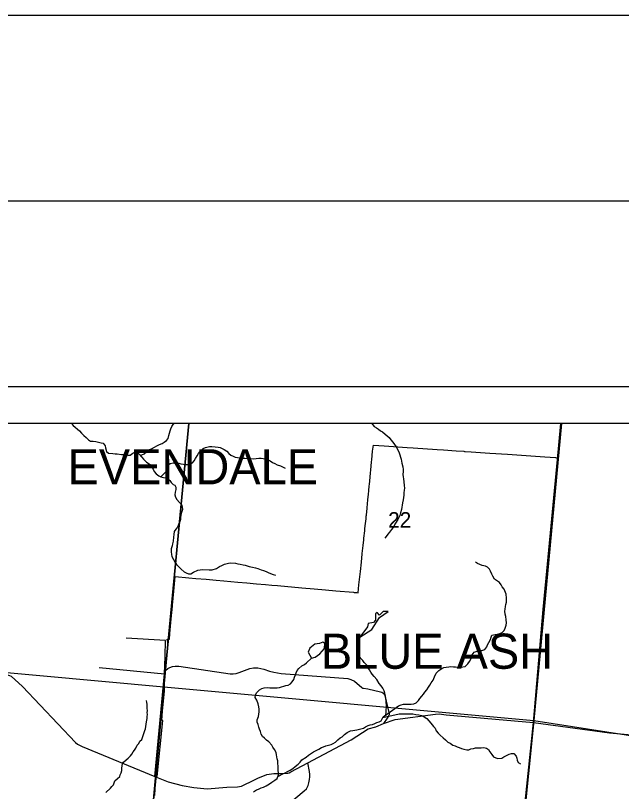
# Model space of a CAD drawing. Extents: x 0 to 34, y -3.9 to 26.2.
# Drawn here: x 4.778 to 6.412, y 19.908 to 22 of the extents above; entities that cross this region are included whole.
import ezdxf

# ---------------------------------------------------------------- set-up
doc = ezdxf.new("R2010")
doc.units = 0
for name, color, linetype in [('GM_X_City_Street', 7, 'Continuous'), ('GM_X_Corporation_Text', 7, 'Continuous'), ('GM_X_County_Road', 7, 'Continuous'), ('GM_X_Interchange_Ramps', 7, 'Continuous'), ('GM_X_Interstate_Route', 7, 'Continuous'), ('GM_X_Minor_Lake', 7, 'Continuous'), ('GM_X_Minor_River', 7, 'Continuous'), ('GM_X_Section', 7, 'Continuous'), ('GM_X_Section_Text', 7, 'Continuous'), ('GM_X_State_Shield', 7, 'Continuous'), ('SH_Border', 7, 'Continuous'), ('SH_Cut_Line', 7, 'Continuous'), ('SH_Data', 7, 'Continuous')]:
    doc.layers.add(name, color=color, linetype=linetype)

msp = doc.modelspace()

# ---------------------------------------------------------------- linework, layer by layer
at = {"layer": 'GM_X_City_Street'}
for p, q in [((6.2393, 20.8032), (6.2483, 20.9)), ((5.0032, 20.2422), (5.1797, 20.2252))]:
    msp.add_line(p, q, dxfattribs=at)
for points in [[(6.2305, 19.6109), (6.2157, 19.6127), (6.1964, 19.617), (6.1806, 19.6226), (6.1712, 19.6285), (6.163, 19.6348), (6.1565, 19.6421), (6.1533, 19.6464), (6.1505, 19.6517), (6.1459, 19.665), (6.1443, 19.6717), (6.1419, 19.6812), (6.1399, 19.6998), (6.1394, 19.7226), (6.1444, 19.8016), (6.1745, 20.0934), (6.2008, 20.3987), (6.2393, 20.8032)], [(5.1797, 20.2252), (5.1811, 20.2714), (5.1826, 20.3148), (5.076, 20.321)], [(5.1535, 19.9477), (5.1797, 20.2252), (5.1828, 20.2339), (5.1882, 20.2391), (5.1936, 20.2424), (5.2016, 20.2449), (5.2088, 20.2455), (5.2183, 20.2453), (5.3565, 20.2252), (5.3652, 20.2247), (5.3728, 20.2256), (5.3808, 20.2289), (5.4099, 20.2393), (5.4194, 20.2414), (5.4316, 20.2415), (5.4478, 20.2373), (5.4629, 20.2321), (5.4746, 20.2292), (5.4939, 20.2257), (5.6739, 20.212), (5.6819, 20.2099), (5.6924, 20.2051), (5.7114, 20.188), (5.7142, 20.1864), (5.7163, 20.186), (5.728, 20.1846), (5.762, 20.1767), (5.7654, 20.1754), (5.7681, 20.1739), (5.7715, 20.1706), (5.7733, 20.1681), (5.774, 20.1668), (5.7859, 20.1173), (5.7859, 20.1166), (5.7854, 20.1147), (5.7847, 20.1128), (5.7804, 20.1056), (5.7702, 20.091)], [(5.4375, 19.7631), (5.442, 19.7697), (5.468, 19.808), (5.4947, 19.853), (5.5041, 19.865), (5.5168, 19.8761), (5.5562, 19.9095), (5.5623, 19.9152), (5.5647, 19.9188), (5.5668, 19.9243), (5.5688, 19.9312), (5.5706, 19.9398), (5.5714, 19.9471), (5.5714, 19.9539), (5.5706, 19.9616), (5.5666, 19.9852)]]:
    msp.add_lwpolyline(points, dxfattribs=at)
at = {"layer": 'GM_X_County_Road'}
msp.add_line((6.1745, 20.0934), (6.3797, 20.0659), dxfattribs=at)
for points in [[(4.3628, 20.2608), (4.7594, 20.2214), (4.7613, 20.2207), (4.7666, 20.2189), (4.7965, 20.1906), (4.9395, 20.0396), (4.9451, 20.0349), (4.9572, 20.0286), (5.1535, 19.9477)], [(5.1535, 19.9477), (5.1896, 19.9336), (5.227, 19.9241), (5.2592, 19.9181), (5.2948, 19.9147), (5.3473, 19.9196), (5.3765, 19.9201), (5.3873, 19.9223), (5.3948, 19.9254), (5.4155, 19.9356), (5.4313, 19.9437), (5.4558, 19.9534), (5.4748, 19.956), (5.4983, 19.9563), (5.51, 19.9568), (5.512, 19.9571), (5.5159, 19.9584), (5.5204, 19.9604), (5.5358, 19.9688), (5.5666, 19.9852), (5.6828, 20.0473), (5.7285, 20.0771), (5.7499, 20.082), (5.7702, 20.091), (5.8015, 20.1018), (5.9104, 20.1162), (5.9207, 20.1167), (5.9396, 20.1148), (6.1745, 20.0934)], [(6.3797, 20.0659), (6.4489, 20.0597), (6.5081, 20.0476)]]:
    msp.add_lwpolyline(points, dxfattribs=at)
at = {"layer": 'GM_X_Interchange_Ramps'}
msp.add_lwpolyline([(5.1532, 19.8973), (5.1549, 19.9158), (5.1576, 19.9437), (5.1579, 19.9491), (5.1602, 19.948), (5.1754, 20.0993), (5.1721, 20.0997), (5.1744, 20.1241), (5.1796, 20.1794), (5.1799, 20.1851), (5.18, 20.2008), (5.1804, 20.2075), (5.1842, 20.2474), (5.1897, 20.3059), (5.1865, 20.3188), (5.1927, 20.3183), (5.1941, 20.3337), (5.1959, 20.3535), (5.1968, 20.3632), (5.1977, 20.3723), (5.1994, 20.3911), (5.2, 20.3967), (5.2012, 20.41), (5.2029, 20.4289), (5.2047, 20.4477), (5.2084, 20.4873), (5.2452, 20.484), (5.2641, 20.4824), (5.2924, 20.4799), (5.3186, 20.4776), (5.3394, 20.4758), (5.3584, 20.4741), (5.3773, 20.4724), (5.4021, 20.4702), (5.4274, 20.468), (5.452, 20.4658), (5.4694, 20.4643), (5.4848, 20.463), (5.5504, 20.4572), (5.5833, 20.4543), (5.6135, 20.4516), (5.6418, 20.4491), (5.6894, 20.4449), (5.6908, 20.4447), (5.698, 20.4441), (5.7017, 20.4438), (5.704, 20.4652), (5.7078, 20.5007), (5.7105, 20.5258), (5.7129, 20.5482), (5.713, 20.5491), (5.7153, 20.5709), (5.717, 20.5863), (5.7174, 20.5904), (5.7196, 20.6109), (5.7203, 20.6172), (5.7217, 20.6305), (5.7231, 20.6427), (5.7238, 20.6501), (5.724, 20.6525), (5.725, 20.6624), (5.7259, 20.6711), (5.726, 20.6726), (5.7281, 20.6944), (5.7296, 20.7096), (5.7304, 20.7186), (5.7317, 20.7322), (5.7321, 20.7359), (5.734, 20.7551), (5.7351, 20.7671), (5.7359, 20.7743), (5.7382, 20.7968), (5.7387, 20.802), (5.7409, 20.8252), (5.7429, 20.8417), (5.7717, 20.8397), (5.8342, 20.8354), (5.8499, 20.8344), (5.9151, 20.8299), (5.9321, 20.8287), (5.9661, 20.8264), (5.9865, 20.825), (5.9888, 20.8248), (5.9903, 20.8247), (6.0069, 20.8236), (6.0443, 20.821), (6.0572, 20.8201), (6.105, 20.8169), (6.2053, 20.81), (6.2341, 20.808), (6.2367, 20.8078), (6.2424, 20.8074), (6.2473, 20.8629), (6.2507, 20.9), (3.4963, 20.9)], dxfattribs=at)
at = {"layer": 'GM_X_Interstate_Route'}
msp.add_lwpolyline([(8.9, 20.9), (3.1989, 20.9)], dxfattribs=at)
at = {"layer": 'GM_X_Minor_Lake'}
for p, q in [((5.727, 20.3513), (5.7067, 20.3234)), ((5.5669, 20.2838), (5.576, 20.2668))]:
    msp.add_line(p, q, dxfattribs=at)
for points in [[(5.7067, 20.3234), (5.7391, 20.3446), (5.7591, 20.3768), (5.7826, 20.3931), (5.7693, 20.3926), (5.7592, 20.3829), (5.7529, 20.3899), (5.7483, 20.3869), (5.7483, 20.3698), (5.7429, 20.3631), (5.7291, 20.3611), (5.727, 20.3513)], [(5.576, 20.2668), (5.5856, 20.2701), (5.5983, 20.279), (5.6107, 20.2932), (5.6118, 20.3064), (5.6069, 20.3107), (5.5977, 20.3071), (5.5851, 20.3051), (5.572, 20.2943), (5.5669, 20.2838)]]:
    msp.add_lwpolyline(points, dxfattribs=at)
at = {"layer": 'GM_X_Minor_River'}
for points in [[(4.9291, 20.9), (4.9338, 20.8945), (4.939, 20.8905), (4.9453, 20.8849), (4.9504, 20.8798), (4.9558, 20.8735), (4.962, 20.8675), (4.9687, 20.8623), (4.9745, 20.856), (4.9805, 20.8527), (4.9873, 20.8524), (4.9945, 20.8513), (5.0013, 20.8499), (5.0092, 20.8481), (5.0144, 20.8467), (5.0198, 20.8396), (5.0208, 20.8343), (5.023, 20.8243), (5.0286, 20.8199), (5.0399, 20.819), (5.0464, 20.8184), (5.052, 20.8178), (5.0638, 20.8165), (5.0695, 20.8163), (5.0748, 20.8153), (5.0808, 20.8143), (5.0869, 20.8148), (5.0947, 20.8198), (5.1001, 20.823), (5.1062, 20.8224), (5.1128, 20.8156), (5.1186, 20.8089), (5.1233, 20.8034), (5.1314, 20.7959), (5.141, 20.789), (5.1449, 20.7835), (5.1489, 20.7769), (5.1517, 20.7707), (5.1575, 20.7644), (5.1648, 20.7584), (5.1701, 20.7559), (5.1772, 20.7544), (5.1836, 20.753), (5.1893, 20.7509), (5.1944, 20.7465), (5.1972, 20.7407), (5.2027, 20.7355), (5.2079, 20.7334), (5.2104, 20.7279), (5.2102, 20.7223), (5.2087, 20.7147), (5.2077, 20.7079), (5.209, 20.7014), (5.2125, 20.6952), (5.2198, 20.6865), (5.2253, 20.6813), (5.2269, 20.6756), (5.2278, 20.6683), (5.2243, 20.657), (5.2233, 20.6518), (5.2227, 20.6461), (5.2225, 20.6408), (5.2212, 20.6355), (5.2174, 20.6273), (5.2145, 20.6206), (5.2101, 20.6147), (5.2061, 20.6084), (5.205, 20.6008), (5.2043, 20.5936), (5.2028, 20.5831), (5.2013, 20.5755), (5.2004, 20.5702), (5.1978, 20.5624), (5.1974, 20.5536), (5.1987, 20.5467), (5.1996, 20.5414), (5.2035, 20.5332), (5.2085, 20.5254), (5.2121, 20.5196), (5.2194, 20.5128), (5.2248, 20.5069), (5.2329, 20.4997), (5.2381, 20.4972), (5.2441, 20.495), (5.2506, 20.4948), (5.258, 20.4994), (5.2692, 20.5043), (5.2761, 20.5055), (5.2822, 20.506), (5.3004, 20.5052), (5.3084, 20.5057), (5.3196, 20.5094), (5.3281, 20.514), (5.3339, 20.5168)], [(5.1141, 20.8141), (5.1246, 20.8182), (5.1309, 20.8232), (5.1391, 20.8294), (5.1446, 20.8318), (5.1523, 20.836), (5.1589, 20.8396), (5.1663, 20.8431), (5.1733, 20.8462), (5.1791, 20.8498), (5.1846, 20.8537), (5.1894, 20.8596), (5.1916, 20.8675), (5.1933, 20.8739), (5.1947, 20.8799), (5.1969, 20.8859), (5.1997, 20.8915), (5.2034, 20.897), (5.2055, 20.9)], [(5.7382, 20.9), (5.7385, 20.8995), (5.7451, 20.892), (5.7514, 20.8883), (5.757, 20.885), (5.7625, 20.8806), (5.7677, 20.8774), (5.7747, 20.8714), (5.7802, 20.8666), (5.7853, 20.8618), (5.7904, 20.8559), (5.7951, 20.85), (5.8002, 20.8429), (5.8048, 20.8367), (5.8087, 20.8285), (5.8126, 20.8211), (5.8147, 20.8157), (5.8159, 20.8096), (5.8176, 20.8042), (5.8186, 20.7988), (5.8198, 20.7931), (5.8221, 20.7835), (5.8234, 20.7762), (5.8235, 20.7709), (5.8228, 20.7622), (5.8229, 20.7561), (5.8239, 20.7503), (5.8247, 20.7431), (5.8262, 20.7331), (5.8267, 20.7259), (5.8261, 20.7198), (5.8254, 20.713), (5.8248, 20.707), (5.8242, 20.7001), (5.8232, 20.6941), (5.8213, 20.6858), (5.8207, 20.6798), (5.8197, 20.6745), (5.8187, 20.6677), (5.8164, 20.6587), (5.8147, 20.6523), (5.8114, 20.6463), (5.8089, 20.6411), (5.8041, 20.6337), (5.8008, 20.6281), (5.7983, 20.6225), (5.7915, 20.6137), (5.7863, 20.6071), (5.7819, 20.6019), (5.7775, 20.5957), (5.7742, 20.5905)], [(5.1701, 20.7559), (5.184, 20.7709), (5.1862, 20.7803), (5.188, 20.7863), (5.1947, 20.7917), (5.2031, 20.794), (5.2126, 20.7932), (5.2179, 20.7926), (5.2235, 20.7913), (5.2307, 20.7906), (5.2375, 20.7895), (5.244, 20.7897), (5.2494, 20.7909), (5.2552, 20.7937), (5.2596, 20.7989), (5.2636, 20.8056), (5.2673, 20.813), (5.271, 20.8193), (5.277, 20.8263), (5.284, 20.8321), (5.2899, 20.8353), (5.3006, 20.8382), (5.3071, 20.8383), (5.3162, 20.8372), (5.3241, 20.8365), (5.3298, 20.8351), (5.3354, 20.8326), (5.3406, 20.8297), (5.3476, 20.8256), (5.3531, 20.8193), (5.3582, 20.8146), (5.3646, 20.812), (5.3706, 20.8095), (5.3762, 20.8081), (5.3826, 20.8075), (5.3894, 20.8068), (5.3959, 20.8061), (5.4027, 20.8059), (5.4099, 20.8052), (5.4194, 20.8048), (5.4266, 20.8052), (5.4339, 20.8065), (5.4403, 20.8062), (5.4456, 20.8056), (5.4513, 20.805), (5.4573, 20.8028), (5.4644, 20.7991), (5.4711, 20.795), (5.4774, 20.7921), (5.4837, 20.7888), (5.4927, 20.7854), (5.4994, 20.7821), (5.5054, 20.7795)], [(5.7719, 20.1111), (5.8107, 20.1385), (5.8181, 20.1416), (5.8246, 20.1432), (5.8326, 20.1429), (5.8447, 20.1428), (5.8516, 20.144), (5.8586, 20.1468), (5.8649, 20.153), (5.8685, 20.1585), (5.8737, 20.1644), (5.8785, 20.1699), (5.8821, 20.1758), (5.8873, 20.1821), (5.8918, 20.1891), (5.8954, 20.1946), (5.8991, 20.2006), (5.9043, 20.208), (5.9077, 20.2169), (5.9123, 20.2266), (5.9198, 20.2339), (5.9276, 20.2389), (5.933, 20.2417), (5.9395, 20.243), (5.946, 20.2439), (5.9521, 20.2447), (5.9586, 20.2441), (5.9646, 20.2438), (5.9714, 20.2432), (5.9787, 20.2429), (5.9844, 20.2434), (5.9901, 20.2443), (5.9976, 20.2516), (6.0024, 20.2579), (6.0057, 20.2646), (6.0071, 20.2698), (6.0089, 20.2766), (6.0144, 20.2832), (6.0229, 20.2863), (6.0298, 20.2879), (6.0351, 20.2877), (6.0432, 20.2904), (6.0488, 20.2974), (6.0506, 20.3034), (6.0542, 20.3093), (6.0587, 20.3175), (6.0605, 20.3239), (6.0622, 20.3291), (6.0718, 20.331), (6.0775, 20.3319), (6.0837, 20.3339), (6.0899, 20.3367), (6.0958, 20.3418), (6.0987, 20.3481), (6.1006, 20.3564), (6.1015, 20.3621), (6.1007, 20.3709), (6.0999, 20.3793), (6.0983, 20.3862), (6.0978, 20.3938), (6.0984, 20.3991), (6.0995, 20.4066), (6.1005, 20.4123), (6.1015, 20.4183), (6.1015, 20.4294), (6.1008, 20.4397), (6.096, 20.4535), (6.0902, 20.4595), (6.0874, 20.4653), (6.0834, 20.4708), (6.0778, 20.4744), (6.0697, 20.4805), (6.0647, 20.4887), (6.0627, 20.4941), (6.0592, 20.5018), (6.056, 20.5073), (6.0508, 20.5124), (6.0449, 20.5153), (6.0362, 20.5168), (6.0298, 20.5194), (6.0235, 20.5227), (6.0183, 20.5263)], [(5.3339, 20.5168), (5.3413, 20.521), (5.3524, 20.5232), (5.3586, 20.5245), (5.3714, 20.5232), (5.3778, 20.5218), (5.3839, 20.5208), (5.3918, 20.5189), (5.3974, 20.5176), (5.4027, 20.5158), (5.4083, 20.5148), (5.4174, 20.5129), (5.4249, 20.5111), (5.4317, 20.5093), (5.4406, 20.5055), (5.4467, 20.5037), (5.4534, 20.5012), (5.4608, 20.4974), (5.4728, 20.4931), (5.4792, 20.491)], [(5.4848, 19.9468), (5.4968, 19.9546), (5.5053, 19.9581), (5.5115, 19.9616), (5.5185, 19.9651), (5.5259, 19.9694), (5.5318, 19.9748), (5.5397, 19.9817), (5.5452, 19.9872), (5.5504, 19.9931), (5.5613, 20.0002), (5.5676, 20.0053), (5.5738, 20.0092), (5.5816, 20.0142), (5.589, 20.0185), (5.596, 20.022), (5.6026, 20.0259), (5.608, 20.0279), (5.615, 20.0307), (5.6223, 20.0327), (5.6288, 20.0347), (5.6342, 20.0367), (5.6404, 20.0406), (5.6475, 20.0468), (5.6531, 20.0523), (5.6585, 20.0555), (5.6648, 20.0617), (5.6726, 20.0667), (5.6815, 20.0713), (5.6873, 20.0722), (5.6927, 20.0735), (5.698, 20.074), (5.7091, 20.0766), (5.7164, 20.0782), (5.7219, 20.0821), (5.7285, 20.0853), (5.7342, 20.0873), (5.7404, 20.0882), (5.7469, 20.0906), (5.7523, 20.0934), (5.7589, 20.0958), (5.7643, 20.0986), (5.7668, 20.1038), (5.7697, 20.1094), (5.7767, 20.1148), (5.7774, 20.122), (5.7782, 20.141), (5.7776, 20.1467), (5.7775, 20.152), (5.7769, 20.1581), (5.7753, 20.1654), (5.7737, 20.1731), (5.7717, 20.1793), (5.7682, 20.1863), (5.7635, 20.1922), (5.7588, 20.1992), (5.7524, 20.2097), (5.7447, 20.218), (5.7393, 20.2243), (5.7361, 20.2298), (5.7325, 20.2356), (5.7282, 20.2423), (5.725, 20.2485), (5.7184, 20.2552), (5.7145, 20.2607), (5.7094, 20.2659), (5.7036, 20.2741), (5.7001, 20.2807), (5.6991, 20.2861), (5.6994, 20.2933), (5.7009, 20.3023), (5.7027, 20.3095), (5.7037, 20.3159), (5.7067, 20.3234)], [(5.5303, 20.2159), (5.5328, 20.2223), (5.5346, 20.2275), (5.5375, 20.2335), (5.5423, 20.2394), (5.5501, 20.2466), (5.5568, 20.2505), (5.563, 20.2548), (5.576, 20.2668)], [(5.4197, 19.9069), (5.4279, 19.9123), (5.4333, 19.9143), (5.4402, 19.9174), (5.4464, 19.9195), (5.4538, 19.923), (5.4627, 19.9287), (5.469, 19.9326), (5.4772, 19.9383), (5.4834, 19.9426), (5.4869, 19.9528), (5.4867, 19.9585), (5.4862, 19.9638), (5.486, 19.9703), (5.4859, 19.976), (5.4854, 19.9836), (5.4849, 19.9901), (5.4836, 19.9962), (5.4818, 20.0062), (5.4805, 20.0131), (5.4763, 20.0212), (5.4719, 20.0271), (5.4687, 20.0326), (5.4611, 20.0413), (5.4548, 20.0465), (5.4493, 20.0513), (5.4442, 20.0557), (5.4407, 20.0626), (5.4383, 20.0696), (5.4362, 20.0754), (5.4338, 20.0812), (5.4326, 20.0884), (5.4294, 20.0943), (5.4292, 20.1007), (5.433, 20.1101), (5.4344, 20.1161), (5.4351, 20.1229), (5.4353, 20.1294), (5.4344, 20.1359), (5.4325, 20.1439), (5.4287, 20.154), (5.4244, 20.1614), (5.4254, 20.1671), (5.4279, 20.1738), (5.4359, 20.1818), (5.4421, 20.1857), (5.4482, 20.1874), (5.4585, 20.1877), (5.4638, 20.1871), (5.4695, 20.1873), (5.4763, 20.187), (5.4832, 20.1875), (5.4901, 20.1883), (5.4955, 20.19), (5.5016, 20.192), (5.507, 20.1933), (5.5127, 20.1942), (5.5197, 20.1977), (5.5241, 20.2032), (5.5282, 20.2095), (5.5303, 20.2159)], [(5.0214, 19.9048), (5.034, 19.9165), (5.0376, 19.9209), (5.042, 19.926), (5.0437, 19.9313), (5.0461, 19.9361), (5.0532, 19.9427), (5.0588, 19.9481), (5.0605, 19.953), (5.063, 19.9582), (5.0644, 19.9646), (5.065, 19.9699), (5.0656, 19.9775), (5.0662, 19.982), (5.0691, 19.9872), (5.0765, 19.9934), (5.0816, 19.9974), (5.0876, 20.0039), (5.0912, 20.0084), (5.0956, 20.0143), (5.0988, 20.0187), (5.1021, 20.0243), (5.1062, 20.0328), (5.1106, 20.0372), (5.1135, 20.0432), (5.1186, 20.0475), (5.1207, 20.0535), (5.1233, 20.061), (5.125, 20.0666), (5.1267, 20.0719), (5.1281, 20.0768), (5.1295, 20.0828), (5.1305, 20.0896), (5.1311, 20.0957), (5.1326, 20.1043), (5.1328, 20.1097), (5.1334, 20.1149), (5.1332, 20.1203), (5.1334, 20.1252), (5.1333, 20.1324), (5.1328, 20.1385), (5.1326, 20.1435), (5.1324, 20.1481), (5.1307, 20.1535)], [(5.7686, 20.1073), (5.8122, 20.1175), (5.8194, 20.1168), (5.8312, 20.1167), (5.8403, 20.1171), (5.8494, 20.1167), (5.8573, 20.1156), (5.8656, 20.1142), (5.8724, 20.1127), (5.8803, 20.109), (5.8869, 20.1045), (5.8928, 20.0982), (5.8978, 20.0915), (5.9047, 20.0833), (5.9098, 20.0781), (5.9122, 20.0715), (5.918, 20.0648), (5.9232, 20.0597), (5.9309, 20.0525), (5.9371, 20.0466), (5.9441, 20.0409), (5.95, 20.038), (5.9574, 20.0328), (5.9635, 20.031), (5.969, 20.0277), (5.9743, 20.0264), (5.9803, 20.0235), (5.9866, 20.0217), (5.9946, 20.0202), (6.0007, 20.0203), (6.0061, 20.0224), (6.0126, 20.024), (6.0183, 20.0253), (6.0248, 20.0258), (6.0332, 20.0258), (6.0408, 20.0259), (6.048, 20.0248), (6.0535, 20.0208), (6.0567, 20.0146), (6.0621, 20.0072), (6.0668, 20.0016), (6.0731, 19.9983), (6.0784, 19.997), (6.0895, 19.998), (6.0949, 20.0012), (6.1019, 20.0051), (6.1089, 20.0082), (6.1154, 20.0106), (6.1219, 20.0104), (6.128, 20.0033), (6.1297, 19.9975), (6.1306, 19.9918), (6.1338, 19.9863), (6.1397, 19.9819)]]:
    msp.add_lwpolyline(points, dxfattribs=at)
at = {"layer": 'GM_X_Section'}
for points in [[(4.1738, 20.2814), (5.1778, 20.1897), (5.0852, 19.1785), (4.0751, 19.2669)], [(5.1778, 20.1897), (6.1758, 20.0989), (6.0727, 19.072), (5.0852, 19.1785)], [(6.1758, 20.0989), (7.2234, 19.9362), (7.1209, 18.9374), (6.0727, 19.072)]]:
    msp.add_lwpolyline(points, close=True, dxfattribs=at)
at = {"layer": 'GM_X_State_Shield'}
for points in [[(5.2454, 20.9), (4.2313, 20.9), (4.1738, 20.2814), (5.1778, 20.1897)], [(6.2505, 20.9), (5.2454, 20.9), (5.1778, 20.1897), (6.1758, 20.0989)], [(7.3179, 20.9), (6.2505, 20.9), (6.1758, 20.0989), (7.2234, 19.9362)]]:
    msp.add_lwpolyline(points, close=True, dxfattribs=at)
at = {"layer": 'SH_Border'}
msp.add_lwpolyline([(1.5, 21.5), (33.5, 21.5), (33.5, 0.5), (1.5, 0.5)], close=True, dxfattribs=at)
at = {"layer": 'SH_Cut_Line'}
msp.add_lwpolyline([(0, 0), (34, 0), (34, 22), (0, 22)], close=True, dxfattribs=at)
at = {"layer": 'SH_Data'}
msp.add_line((2, 21), (9, 21), dxfattribs=at)

# ---------------------------------------------------------------- texts
at = {"layer": 'GM_X_Corporation_Text'}
for s, p in [('EVENDALE', (4.9181, 20.736)), ('BLUE ASH', (5.6013, 20.2386))]:
    msp.add_text(s, height=0.0947, rotation=0, dxfattribs=at).set_placement(p)
at = {"layer": 'GM_X_Section_Text'}
msp.add_text('22', height=0.04186, rotation=0, dxfattribs=at).set_placement((5.7827, 20.6191))

doc.saveas('drawing.dxf')
